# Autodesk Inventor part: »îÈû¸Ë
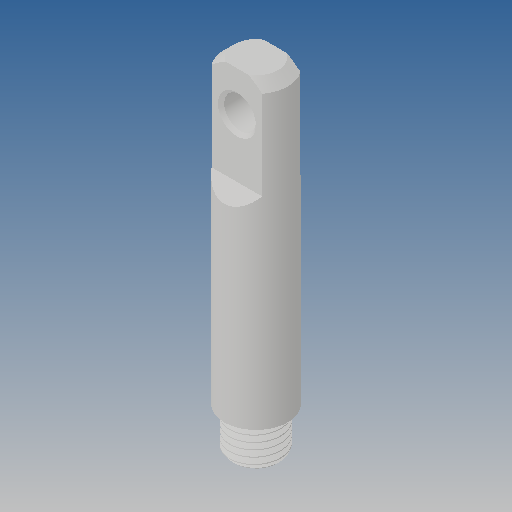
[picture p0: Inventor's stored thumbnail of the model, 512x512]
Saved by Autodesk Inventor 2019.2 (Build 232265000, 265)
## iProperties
Created: 2013-07
Part Number: »îÈû¸Ë
Material: Ogólny
Document SubType Name: Modeling
Designer: CADENGINEERING4
Density: 1 g/cm^3
Appearance: Domyślna
Author: CADENGINEERING4
Revision Number: ÈÎºÎ
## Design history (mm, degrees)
feature "ÇÐ³ý-É¨Ãè1"
node "Bryła1"
